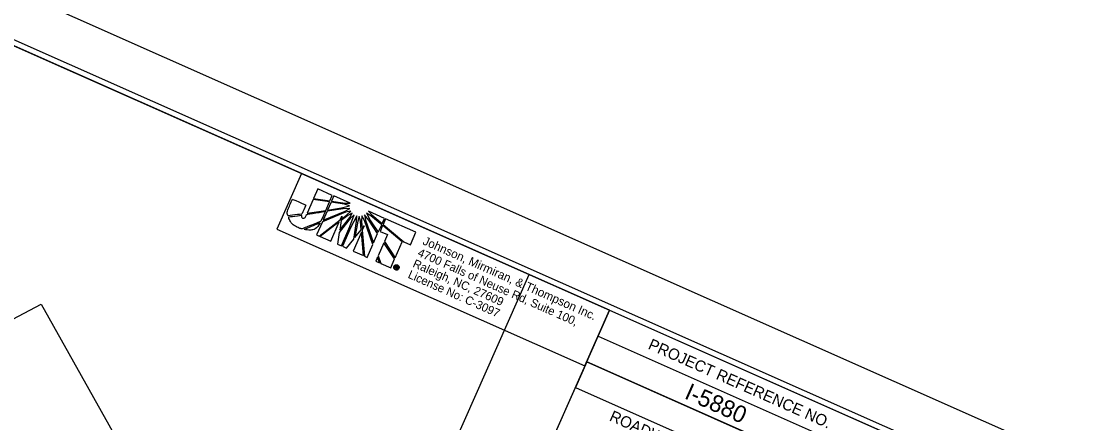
# Model space of a CAD drawing. Extents: x 1638962 to 2864602, y 841929 to 973236.
# Drawn here: x 1640475.6 to 1640945, y 842947 to 843125.5 of the extents above; entities that cross this region are included whole.
import ezdxf

# ---------------------------------------------------------------- set-up
doc = ezdxf.new("R2010")
doc.units = 0
for name, color, linetype in [('DEV STATIONARY SIGN DUAL MOUNT CELL', 7, 'Continuous'), ('Prop EOT', 7, 'Continuous'), ('Prop Mkg Min Skp 6ft White', 7, 'Continuous'), ('Prop Mkg Solid White Edge Line', 7, 'Continuous'), ('Prop Paved Shoulder', 7, 'Continuous'), ('Prop Roadway Bridge', 7, 'Continuous'), ('Sheet Symbology CELL', 7, 'Continuous')]:
    doc.layers.add(name, color=color, linetype=linetype)

msp = doc.modelspace()

# ---------------------------------------------------------------- linework, layer by layer
at = {"layer": 'DEV STATIONARY SIGN DUAL MOUNT CELL'}
for p, q in [((1640732.38, 842985.57), (1640915.25, 842904.47)), ((1640727.3, 842974.1), (1640722.24, 842962.69)), ((1640727.3, 842974.1), (1640910.18, 842893.04)), ((1640727.3, 842974.1), (1640910.18, 842893.04))]:
    msp.add_line(p, q, dxfattribs=at)
for points in [[(1640920.37, 842915.92), (1639549.09, 843523.96), (1639123.48, 842564.09), (1640494.73, 841956.06)], [(1639123.48, 842564.09), (1639549.06, 843523.95), (1640737.47, 842997.04), (1640676.66, 842859.85), (1640859.52, 842778.75), (1640494.73, 841956.06)], [(1640737.47, 842997.04), (1640920.37, 842915.92), (1640910.18, 842893.04), (1640727.3, 842974.1)], [(1640722.24, 842962.69), (1640813.7, 842922.13), (1640768.1, 842819.28), (1640676.66, 842859.85)]]:
    msp.add_lwpolyline(points, close=True, dxfattribs=at)
at = {"layer": 'Prop EOT'}
msp.add_lwpolyline([(1639169.19, 842543.82), (1640449.02, 841976.33), (1640788.91, 842742.87), (1640615.9, 842819.58), (1640701.62, 843012.92), (1639594.8, 843503.69)], close=True, dxfattribs=at)
msp.add_lwpolyline([(1639574.53, 843457.96), (1639704.62, 843430.63), (1639732.25, 843400.48), (1639712.8, 843352.82), (1639717.32, 843351.5), (1639822.84, 843303.26), (1639837.7, 843339.42), (1639864.3, 843376.29), (1639864.3, 843376.29), (1639968.61, 843321.42), (1639881.29, 843210.54), (1640149.46, 843094.59), (1640219.3, 843062.65), (1640227.76, 843057.7), (1640297.65, 843026.04), (1640368.11, 842995.95), (1640397.09, 842983.33), (1640403.3, 842975.95), (1640421.83, 842966.71), (1640484.57, 842999.74), (1640629.05, 842742.44), (1640617.73, 842617.59)], dxfattribs=at)
at = {"layer": 'Prop Mkg Solid White Edge Line'}
msp.add_lwpolyline([(1640484.57, 842999.74), (1640629.05, 842742.44), (1640617.74, 842617.54)], dxfattribs=at)
at = {"layer": 'Prop Paved Shoulder'}
msp.add_lwpolyline([(1638982.15, 842624.01), (1640505.14, 841948.72), (1640932.78, 842913.14), (1639409.79, 843588.45)], close=True, dxfattribs=at)
at = {"layer": 'Prop Roadway Bridge'}
msp.add_lwpolyline([(1638962.15, 842610.99), (1640501.15, 841928.59), (1640945, 842929.6), (1639406.01, 843612)], close=True, dxfattribs=at)
msp.add_lwpolyline([(1638962.15, 842610.99), (1640501.15, 841928.59), (1640945, 842929.6), (1639406.01, 843612)], close=True, dxfattribs=at)
at = {"layer": 'Sheet Symbology CELL'}
for p, q in [((1640607.66, 843050.96), (1640605.77, 843046.7)), ((1640614.08, 843048.12), (1640607.66, 843050.96)), ((1640605.56, 843046.22), (1640602.91, 843040.23)), ((1640612.78, 843045.18), (1640605.56, 843046.22)), ((1640605.77, 843046.7), (1640612.98, 843045.64)), ((1640612.98, 843045.64), (1640614.08, 843048.12)), ((1640614.76, 843047.86), (1640613.74, 843045.56)), ((1640621.99, 843044.66), (1640614.76, 843047.86)), ((1640602.91, 843040.23), (1640611.13, 843041.46)), ((1640611.13, 843041.46), (1640612.78, 843045.18)), ((1640618.87, 843042.1), (1640611.74, 843041.03)), ((1640613.52, 843045.06), (1640611.99, 843041.59)), ((1640611.99, 843041.59), (1640618.16, 843042.51)), ((1640619.56, 843044.17), (1640613.52, 843045.06)), ((1640613.74, 843045.56), (1640619.78, 843044.66)), ((1640618.16, 843042.51), (1640621.77, 843043.49)), ((1640621.86, 843042.26), (1640618.87, 843042.1)), ((1640621.77, 843043.49), (1640619.56, 843044.17)), ((1640619.78, 843044.66), (1640621.99, 843044.66)), ((1640619.85, 843041.07), (1640621.86, 843042.26)), ((1640608.15, 843030.05), (1640617.59, 843037.21)), ((1640619.97, 843040.6), (1640609.67, 843036.34)), ((1640609.97, 843037.02), (1640619.85, 843041.07)), ((1640611.74, 843041.03), (1640609.97, 843037.02)), ((1640622.07, 843037.76), (1640617.19, 843031.62)), ((1640617.37, 843032.6), (1640621.87, 843038.28)), ((1640618.05, 843036.92), (1640617.37, 843032.6)), ((1640617.59, 843037.21), (1640618.34, 843038.91)), ((1640620.94, 843039.11), (1640618.05, 843036.92)), ((1640618.14, 843037.6), (1640620.57, 843039.45)), ((1640618.34, 843038.91), (1640618.14, 843037.6)), ((1640622.26, 843041.16), (1640619.97, 843040.6)), ((1640620.57, 843039.45), (1640622.26, 843041.16)), ((1640622.93, 843040.18), (1640620.94, 843039.11)), ((1640621.87, 843038.28), (1640622.93, 843040.18)), ((1640621.9, 843034.24), (1640623.86, 843039.43)), ((1640623.86, 843039.43), (1640622.07, 843037.76)), ((1640624.92, 843038.96), (1640622.35, 843034.04)), ((1640624.86, 843036.53), (1640624.92, 843038.96)), ((1640626.08, 843038.79), (1640625.38, 843036.64)), ((1640626.59, 843036.61), (1640626.08, 843038.79)), ((1640627.24, 843038.96), (1640627.12, 843036.56)), ((1640628.37, 843036.89), (1640627.24, 843038.96)), ((1640628.34, 843039.4), (1640628.79, 843037.08)), ((1640630.27, 843037.06), (1640628.34, 843039.4)), ((1640632.12, 843026.34), (1640628.37, 843036.89)), ((1640628.79, 843037.08), (1640632.42, 843027)), ((1640629.34, 843040.15), (1640631.05, 843036.75)), ((1640631.21, 843039.02), (1640629.34, 843040.15)), ((1640637.27, 843037.87), (1640630.17, 843041.05)), ((1640630.17, 843041.05), (1640631.59, 843039.4)), ((1640634.24, 843031.11), (1640630.27, 843037.06)), ((1640631.05, 843036.75), (1640634.49, 843031.69)), ((1640636.04, 843035.07), (1640631.21, 843039.02)), ((1640631.59, 843039.4), (1640636.25, 843035.56)), ((1640636.25, 843035.56), (1640637.27, 843037.87)), ((1640637.78, 843037.68), (1640636.69, 843035.2)), ((1640651.28, 843031.71), (1640637.78, 843037.68)), ((1640609.67, 843036.34), (1640607.09, 843030.52)), ((1640617.18, 843036.29), (1640608.65, 843029.83)), ((1640613.44, 843027.71), (1640617.18, 843036.29)), ((1640618.11, 843025.68), (1640621.9, 843034.24)), ((1640622.35, 843034.04), (1640618.57, 843025.48)), ((1640623.59, 843028.67), (1640624.86, 843036.53)), ((1640625.38, 843036.64), (1640624.17, 843029.42)), ((1640624.17, 843029.42), (1640626.93, 843032.86)), ((1640626.93, 843032.86), (1640626.59, 843036.61)), ((1640627.12, 843036.56), (1640627.36, 843033.39)), ((1640627.36, 843033.39), (1640628.25, 843034.52)), ((1640628.25, 843034.52), (1640627.43, 843032.64)), ((1640627.43, 843032.64), (1640628.44, 843021.07)), ((1640634.49, 843031.69), (1640636.04, 843035.07)), ((1640636.47, 843034.7), (1640635.32, 843032.11)), ((1640635.32, 843032.11), (1640638.62, 843030.66)), ((1640636.49, 843034.74), (1640636.47, 843034.7)), ((1640645.18, 843027.5), (1640636.49, 843034.74)), ((1640636.69, 843035.2), (1640636.66, 843035.12)), ((1640636.66, 843035.12), (1640645.97, 843027.45)), ((1640607.09, 843030.52), (1640608.15, 843030.05)), ((1640608.65, 843029.83), (1640613.44, 843027.71)), ((1640617.19, 843031.62), (1640616.35, 843026.46)), ((1640620.35, 843024.69), (1640623.59, 843028.67)), ((1640627.02, 843031.72), (1640623.32, 843023.37)), ((1640627.92, 843021.34), (1640627.02, 843031.72)), ((1640632.42, 843027), (1640634.24, 843031.11)), ((1640638.62, 843030.66), (1640637.26, 843027.57)), ((1640637.26, 843027.57), (1640642.04, 843020.41)), ((1640642.04, 843020.41), (1640645.18, 843027.5)), ((1640645.97, 843027.45), (1640648.84, 843026.18)), ((1640648.84, 843026.18), (1640651.28, 843031.71)), ((1640616.35, 843026.46), (1640618.11, 843025.68)), ((1640618.57, 843025.48), (1640620.35, 843024.69)), ((1640623.32, 843023.37), (1640627.92, 843021.34)), ((1640629.57, 843020.57), (1640632.12, 843026.34)), ((1640637.02, 843027.04), (1640634.48, 843021.3)), ((1640641.82, 843019.92), (1640637.02, 843027.04)), ((1640628.44, 843021.07), (1640629.57, 843020.57)), ((1640634.21, 843020.68), (1640633.41, 843018.87)), ((1640633.41, 843018.87), (1640635.07, 843018.14)), ((1640635.07, 843018.14), (1640634.21, 843020.68)), ((1640634.48, 843021.3), (1640635.71, 843017.86)), ((1640640.06, 843015.93), (1640641.82, 843019.92)), ((1640635.71, 843017.86), (1640640.06, 843015.93)), ((1640642.02, 843015.79), (1640642.46, 843016.77)), ((1640642.24, 843015.69), (1640642.02, 843015.79)), ((1640642.25, 843015.23), (1640642.16, 843015.01)), ((1640642.16, 843015.01), (1640642.25, 843015.23)), ((1640642.17, 843015.01), (1640642.16, 843015.01)), ((1640642.41, 843016.08), (1640642.24, 843015.69)), ((1640642.25, 843015.23), (1640642.26, 843015.22)), ((1640642.59, 843016), (1640642.41, 843016.08)), ((1640642.46, 843016.77), (1640642.86, 843016.59)), ((1640642.6, 843016.49), (1640642.49, 843016.25)), ((1640642.49, 843016.25), (1640642.67, 843016.17)), ((1640642.67, 843016.17), (1640642.59, 843016)), ((1640642.59, 843016), (1640642.67, 843016.17)), ((1640642.6, 843015.99), (1640642.59, 843016)), ((1640642.77, 843016.41), (1640642.6, 843016.49)), ((1640642.67, 843016.17), (1640642.68, 843016.17)), ((1640642.86, 843016.59), (1640642.77, 843016.41)), ((1640642.77, 843016.41), (1640642.86, 843016.59)), ((1640642.8, 843016.39), (1640642.77, 843016.41)), ((1640642.86, 843016.59), (1640642.92, 843016.57)), ((1640643.11, 843017.17), (1640643.02, 843016.97)), ((1640643.02, 843016.97), (1640643.11, 843017.17))]:
    msp.add_line(p, q, dxfattribs=at)
msp.add_lwpolyline([(1640589.35, 843033.1), (1640726.5, 842972.29), (1640737.47, 842997.04), (1640600.32, 843057.85)], close=True, dxfattribs=at)
for points in [[(1640605.77, 843046.7), (1640612.98, 843045.64), (1640614.08, 843048.12), (1640607.66, 843050.96), (1640605.77, 843046.7)], [(1640602.91, 843040.23), (1640611.13, 843041.46), (1640612.78, 843045.18), (1640605.56, 843046.22), (1640602.91, 843040.23)], [(1640619.78, 843044.66), (1640621.99, 843044.66), (1640614.76, 843047.86), (1640613.74, 843045.56), (1640619.78, 843044.66)], [(1640611.74, 843041.03), (1640609.97, 843037.02), (1640619.85, 843041.07), (1640621.86, 843042.26), (1640618.87, 843042.1), (1640611.74, 843041.03)], [(1640613.52, 843045.06), (1640611.99, 843041.59), (1640618.16, 843042.51), (1640621.77, 843043.49), (1640619.56, 843044.17), (1640613.52, 843045.06)], [(1640622.26, 843041.16), (1640619.97, 843040.6), (1640609.67, 843036.34), (1640607.09, 843030.52), (1640608.15, 843030.05), (1640617.59, 843037.21), (1640618.34, 843038.91), (1640618.14, 843037.6), (1640620.57, 843039.45), (1640622.26, 843041.16)], [(1640622.07, 843037.76), (1640617.19, 843031.62), (1640616.35, 843026.46), (1640618.11, 843025.68), (1640621.9, 843034.24), (1640623.86, 843039.43), (1640622.07, 843037.76)], [(1640622.93, 843040.18), (1640620.94, 843039.11), (1640618.05, 843036.92), (1640617.37, 843032.6), (1640621.87, 843038.28), (1640622.93, 843040.18)], [(1640624.92, 843038.96), (1640622.35, 843034.04), (1640618.57, 843025.48), (1640620.35, 843024.69), (1640623.59, 843028.67), (1640624.86, 843036.53), (1640624.92, 843038.96)], [(1640626.08, 843038.79), (1640625.38, 843036.64), (1640624.17, 843029.42), (1640626.93, 843032.86), (1640626.59, 843036.61), (1640626.08, 843038.79)], [(1640627.24, 843038.96), (1640627.12, 843036.56), (1640627.36, 843033.39), (1640628.25, 843034.52), (1640627.43, 843032.64), (1640628.44, 843021.07), (1640629.57, 843020.57), (1640632.12, 843026.34), (1640628.37, 843036.89), (1640627.24, 843038.96)], [(1640628.34, 843039.4), (1640628.79, 843037.08), (1640632.42, 843027), (1640634.24, 843031.11), (1640630.27, 843037.06), (1640628.34, 843039.4)], [(1640629.34, 843040.15), (1640631.05, 843036.75), (1640634.49, 843031.69), (1640636.04, 843035.07), (1640631.21, 843039.02), (1640629.34, 843040.15)], [(1640631.59, 843039.4), (1640636.25, 843035.56), (1640637.27, 843037.87), (1640630.17, 843041.05), (1640631.59, 843039.4)], [(1640651.28, 843031.71), (1640637.78, 843037.68), (1640636.69, 843035.2), (1640636.66, 843035.12), (1640645.97, 843027.45), (1640648.84, 843026.18), (1640651.28, 843031.71)], [(1640608.65, 843029.83), (1640613.44, 843027.71), (1640617.18, 843036.29), (1640608.65, 843029.83)], [(1640636.49, 843034.74), (1640636.47, 843034.7), (1640635.32, 843032.11), (1640638.62, 843030.66), (1640637.26, 843027.57), (1640642.04, 843020.41), (1640645.18, 843027.5), (1640636.49, 843034.74)], [(1640623.32, 843023.37), (1640627.92, 843021.34), (1640627.02, 843031.72), (1640623.32, 843023.37)], [(1640637.02, 843027.04), (1640634.48, 843021.3), (1640635.71, 843017.86), (1640640.06, 843015.93), (1640641.82, 843019.92), (1640637.02, 843027.04), (1640637.02, 843027.04)], [(1640633.41, 843018.87), (1640633.41, 843018.87), (1640635.07, 843018.14), (1640634.21, 843020.68), (1640633.41, 843018.87)], [(1640642.95, 843015.65), (1640642.93, 843015.6), (1640642.92, 843015.56), (1640642.91, 843015.53), (1640642.89, 843015.41), (1640642.68, 843015.5)]]:
    msp.add_lwpolyline(points, dxfattribs=at)
for points, degree in [([(1640602.29, 843043.8), (1640602.29, 843043.8), (1640596.34, 843046.43), (1640596.34, 843046.43), (1640596.34, 843046.43), (1640594.7, 843042.71), (1640594.7, 843042.71), (1640594.7, 843042.71), (1640594.52, 843042.32), (1640594.52, 843042.32), (1640594.01, 843041.15), (1640593.98, 843040.06), (1640594.32, 843038.99), (1640594.32, 843038.99), (1640600.51, 843039.79), (1640600.55, 843039.87), (1640600.55, 843039.87), (1640602.29, 843043.8), (1640602.29, 843043.8)], 3), ([(1640600.84, 843038.04), (1640600.46, 843038.21), (1640600.22, 843038.57), (1640600.4, 843039.34), (1640600.4, 843039.34), (1640594.53, 843038.53), (1640594.53, 843038.53), (1640595.29, 843036.4), (1640597.16, 843034.51), (1640599.08, 843033.66), (1640599.58, 843033.44), (1640599.98, 843033.32), (1640600.56, 843033.19), (1640600.56, 843033.19), (1640608.98, 843036.61), (1640608.98, 843036.61), (1640608.98, 843036.61), (1640610.9, 843040.93), (1640610.9, 843040.93), (1640610.9, 843040.93), (1640602.67, 843039.69), (1640602.67, 843039.69), (1640601.95, 843038.07), (1640601.37, 843037.81), (1640600.84, 843038.04)], 3), ([(1640600.84, 843038.04), (1640600.46, 843038.21), (1640600.22, 843038.57), (1640600.4, 843039.34), (1640600.4, 843039.34), (1640594.53, 843038.53), (1640594.53, 843038.53), (1640595.29, 843036.4), (1640597.16, 843034.51), (1640599.08, 843033.66), (1640599.58, 843033.44), (1640599.98, 843033.32), (1640600.56, 843033.19), (1640600.56, 843033.19), (1640608.98, 843036.61), (1640608.98, 843036.61), (1640608.98, 843036.61), (1640610.9, 843040.93), (1640610.9, 843040.93), (1640610.9, 843040.93), (1640602.67, 843039.69), (1640602.67, 843039.69), (1640601.95, 843038.07), (1640601.37, 843037.81), (1640600.84, 843038.04)], 3), ([(1640608.68, 843035.93), (1640608.68, 843035.93), (1640601.4, 843032.98), (1640601.4, 843032.98), (1640604.12, 843032.5), (1640607.27, 843033.04), (1640608.68, 843035.93)], 3), ([(1640642.16, 843015.01), (1640641.86, 843015.14), (1640641.65, 843015.37), (1640641.53, 843015.68), (1640641.41, 843015.98), (1640641.42, 843016.28), (1640641.55, 843016.58), (1640641.69, 843016.89), (1640641.91, 843017.1), (1640642.21, 843017.2), (1640642.51, 843017.31), (1640642.81, 843017.31), (1640643.11, 843017.17)], 3), ([(1640643.02, 843016.97), (1640642.78, 843017.08), (1640642.54, 843017.09), (1640642.3, 843017), (1640642.06, 843016.91), (1640641.87, 843016.73), (1640641.77, 843016.49), (1640641.66, 843016.25), (1640641.65, 843016), (1640641.75, 843015.75), (1640641.84, 843015.51), (1640642.01, 843015.34), (1640642.25, 843015.23)], 3), ([(1640643.74, 843015.62), (1640643.6, 843015.31), (1640643.38, 843015.1), (1640643.08, 843014.98), (1640642.78, 843014.87), (1640642.47, 843014.88), (1640642.17, 843015.01)], 3), ([(1640642.26, 843015.22), (1640642.5, 843015.12), (1640642.74, 843015.11), (1640642.99, 843015.2), (1640643.23, 843015.3), (1640643.42, 843015.47), (1640643.52, 843015.71), (1640643.63, 843015.95), (1640643.64, 843016.21), (1640643.54, 843016.45), (1640643.44, 843016.69), (1640643.27, 843016.86), (1640643.02, 843016.97)], 3), ([(1640642.76, 843015.88), (1640642.74, 843015.91), (1640642.69, 843015.95), (1640642.6, 843015.99)], 2), ([(1640642.68, 843016.17), (1640642.82, 843016.11), (1640642.91, 843016.12), (1640642.95, 843016.2), (1640642.98, 843016.27), (1640642.93, 843016.34), (1640642.8, 843016.39)], 3), ([(1640642.68, 843015.5), (1640642.68, 843015.56), (1640642.68, 843015.62), (1640642.72, 843015.7), (1640642.76, 843015.79), (1640642.77, 843015.84), (1640642.76, 843015.88)], 3), ([(1640642.92, 843016.57), (1640643.17, 843016.46), (1640643.25, 843016.3), (1640643.16, 843016.11), (1640643.12, 843016.02), (1640643.06, 843015.96), (1640642.95, 843015.94)], 3), ([(1640642.95, 843015.94), (1640643, 843015.88), (1640643, 843015.78), (1640642.95, 843015.65)], 2), ([(1640643.11, 843017.17), (1640643.42, 843017.04), (1640643.63, 843016.82), (1640643.75, 843016.52), (1640643.88, 843016.23), (1640643.87, 843015.92), (1640643.74, 843015.62)], 3)]:
    msp.add_open_spline(points, degree=degree, dxfattribs=at)

# ---------------------------------------------------------------- texts
at = {"layer": 'DEV STATIONARY SIGN DUAL MOUNT CELL'}
for s, p in [('PROJECT REFERENCE NO.', (1640754.23, 842980.06)), ('ROADWAY DESIGN', (1640737, 842948.16))]:
    msp.add_text(s, height=5.0001, rotation=336.0871, dxfattribs=at).set_placement(p)
at = {"layer": 'Prop Mkg Min Skp 6ft White'}
msp.add_text('I-5880', height=7.5, rotation=336.0871, dxfattribs=at).set_placement((1640770.36, 842958.03))
at = {"layer": 'Sheet Symbology CELL'}
for s, height, p in [('Johnson, Mirmiran, & Thompson Inc.', 3.8334, (1640653.99, 843026.47)), ('4700 Falls of Neuse Rd, Suite 100, ', 3.7239, (1640651.71, 843021.32)), ('Raleigh, NC, 27609', 3.7239, (1640649.56, 843016.46)), ('License No: C-3097', 3.7239, (1640647.4, 843011.6))]:
    msp.add_text(s, height=height, rotation=336.0871, dxfattribs=at).set_placement(p)

doc.saveas('drawing.dxf')
